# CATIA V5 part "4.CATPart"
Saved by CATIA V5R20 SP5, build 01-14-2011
Part number: 4
Bounding box of the stored display mesh (mm): x -106.5 to -93.5, y -14 to 16, z 3.5 to 16.5
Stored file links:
  F:\CAD\很靠后、\4.CATPart
  F:\CAD\很靠后、\1.CATPart
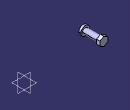
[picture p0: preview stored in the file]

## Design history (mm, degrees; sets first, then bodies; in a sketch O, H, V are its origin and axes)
Body1 (main body)
Body2
  Sketch1 on zx-plane, origin (0, 0, 0), H (-1, 0, 0), V (0, 0, 1)
    circle A1 centre (100, 10) radius 4
    radius A1 = 4
  Pad1: profile Sketch1, direction (0, 1, 0), length 11, mirrored extent
  Sketch2 on start face of Pad1, origin (0, -11, 0), H (1, 0, 0), V (0, 0, 1)
    circle A1 centre (-100, 10) radius 6.5
    radius A1 = 6.5
  Pad2: profile Sketch2, direction (0, -1, 0), length 3
  Sketch3 on end face of Pad1, origin (0, 11, 0), H (-1, 0, 0), V (0, 0, 1)
    point P1 (100, 10)
    point P2 (105.6292, 6.75)
    point P3 (105.6292, 13.25)
    point P4 (100, 16.5)
    point P5 (94.3708, 13.25)
    point P6 (94.3708, 6.75)
    point P7 (100, 3.5)
    point P8 (105.6292, 10)
    line L1 (105.6292, 6.75) -> (105.6292, 13.25)
    line L2 (105.6292, 13.25) -> (100, 16.5)
    line L3 (100, 16.5) -> (94.3708, 13.25)
    line L4 (94.3708, 13.25) -> (94.3708, 6.75)
    line L5 (94.3708, 6.75) -> (100, 3.5)
    line L6 (100, 3.5) -> (105.6292, 6.75)
    construction line L7 (100, 10) -> (105.6292, 10)
    construction circle A1 centre (100, 10) radius 6.5
    construction arc A2 centre (94.3708, 6.75) radius 6.5 from (94.3708, 13.25) to (100, 3.5) cw
    construction arc A3 centre (105.6292, 13.25) radius 6.5 from (100, 16.5) to (105.6292, 6.75) ccw
    radius A1 = 6.5
    coincidence: A1 P2, A1 P3, A1 P4, A1 P5, A1 P6, A1 P7, A2 P1, A3 P1
    midpoint: P8 L1
    parallelism: L1 L4
  Pad3: profile Sketch3, direction (0, 1, 0), length 5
